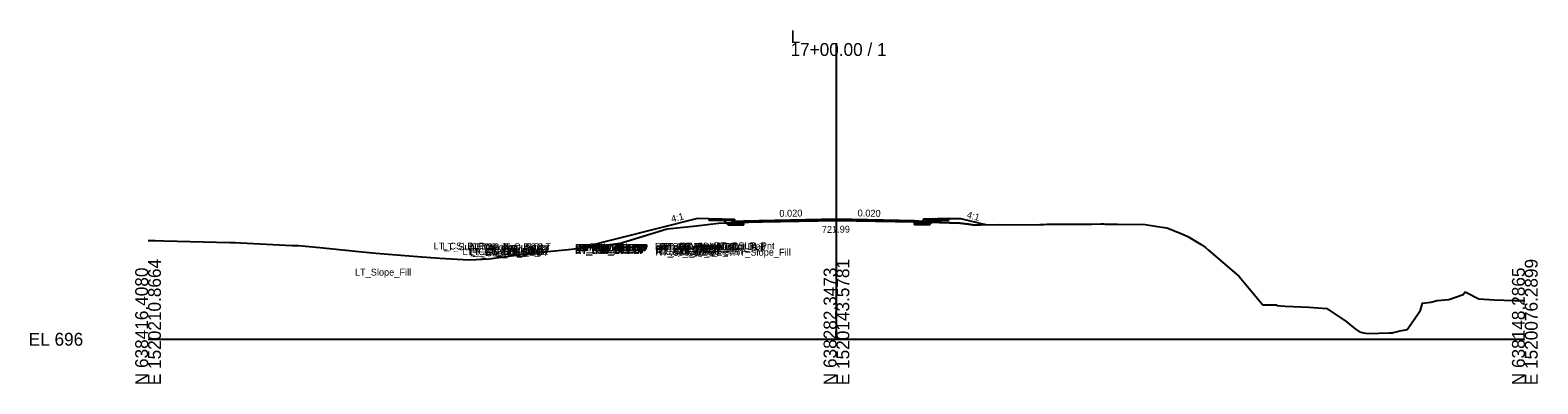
# Model space of a CAD drawing. Extents: x -26 to 3903, y -10 to 9531.
# Drawn here: x -25.7 to 302.8, y 6990.3 to 7067.3 of the extents above; entities that cross this region are included whole.
import ezdxf

# ---------------------------------------------------------------- set-up
doc = ezdxf.new("R2010")
doc.units = 0
for name, color, linetype in [('Default', 7, 'Continuous'), ('Exist Cross Section Cell', 7, 'Continuous'), ('Exist XS Center Line Elevation Label', 7, 'Continuous'), ('Exist XS Ground Line', 7, 'Continuous'), ('Old_Level_63', 7, 'Continuous'), ('Prop CMT Conc Surface', 7, 'Continuous'), ('Prop CMT Pvmt Course 1', 7, 'Continuous'), ('Prop CMT Pvmt Course 1 CG', 7, 'Continuous'), ('Prop CMT Pvmt Course 2', 7, 'Continuous'), ('Prop CMT Pvmt Course 3', 7, 'Continuous'), ('Prop CMT Pvmt Surface', 7, 'Continuous'), ('Prop CMT Slope Grass', 7, 'Continuous'), ('Prop CMT Subgrade Earthwork', 7, 'Continuous'), ('Prop XS Earthwork Shape', 7, 'Continuous'), ('Prop XS SE Text', 7, 'Continuous'), ('Prop XS Side Slope Text', 7, 'Continuous')]:
    doc.layers.add(name, color=color, linetype=linetype)

msp = doc.modelspace()

# ---------------------------------------------------------------- linework, layer by layer
at = {"layer": 'Exist Cross Section Cell'}
for p, q in [((150, 7000), (150, 7064.46)), ((0, 7000), (150, 7000)), ((150, 7000), (300, 7000))]:
    msp.add_line(p, q, dxfattribs=at)
at = {"layer": 'Exist XS Ground Line'}
msp.add_lwpolyline([(0, 7021.49), (0.53, 7021.47), (1.54, 7021.46), (3.41, 7021.42), (17.81, 7021.07), (19, 7021.04), (20.21, 7020.98), (31.36, 7020.42), (32.8, 7020.38), (37.45, 7019.95), (45.2, 7019.18), (49.64, 7018.74), (58.71, 7018), (63.57, 7017.65), (69.89, 7017.26), (71.49, 7017.33), (74.23, 7017.5), (79.68, 7018.24), (80.22, 7018.31), (81.9, 7018.53), (87.14, 7019.09), (91.58, 7019.5), (99.01, 7020.37), (102.77, 7020.89), (102.96, 7020.94), (103.36, 7021.05), (109.58, 7022.93), (113.13, 7024), (119.5, 7024.71), (124.3, 7025.28), (126.6, 7025.35), (127.36, 7025.34), (127.8, 7025.36), (128.35, 7025.38), (129.98, 7025.43), (130.41, 7025.46), (130.82, 7025.46), (131.65, 7025.52), (132.19, 7025.55), (132.5, 7025.55), (133.53, 7025.57), (135.48, 7025.63), (136.32, 7025.65), (137.15, 7025.68), (138.47, 7025.72), (139.13, 7025.74), (140.33, 7025.77), (141.92, 7025.82), (142.73, 7025.84), (144.7, 7025.9), (146.68, 7025.94), (147.49, 7025.96), (148.47, 7025.97), (149.75, 7026), (150.09, 7026), (150.3, 7025.98), (151.52, 7025.97), (153.1, 7025.95), (153.88, 7025.93), (155.89, 7025.89), (157.92, 7025.83), (158.68, 7025.81), (159.84, 7025.79), (160.77, 7025.78), (161, 7025.77), (161.47, 7025.74), (162.66, 7025.7), (164.28, 7025.65), (164.52, 7025.64), (165.01, 7025.62), (167.05, 7025.55), (168.14, 7025.52), (168.57, 7025.51), (168.77, 7025.5), (170.17, 7025.48), (176.87, 7025.25), (178.76, 7025.03), (180.07, 7024.82), (181.45, 7024.92), (185.5, 7025), (191.28, 7024.91), (194.32, 7024.94), (194.58, 7024.97), (195.23, 7024.99), (195.84, 7025.04), (197.24, 7025.06), (198.62, 7025.07), (199.55, 7025.08), (200.01, 7025.08), (201.42, 7025.08), (202.79, 7025.08), (204.14, 7025.08), (205.1, 7025.08), (205.59, 7025.08), (207.61, 7025.09), (208.13, 7025.09), (208.24, 7025.09), (208.55, 7025.08), (209.42, 7025.07), (210.04, 7025.06), (210.82, 7025.06), (210.91, 7025.05), (211.26, 7025.05), (217.28, 7024.98), (219.99, 7024.55), (221.98, 7024.26), (225.13, 7023.03), (226.56, 7022.4), (229.47, 7020.59), (230.45, 7020), (231.05, 7019.36), (237.73, 7013.65), (242.83, 7007.59), (242.9, 7007.5), (242.94, 7007.5), (245.5, 7007.48), (245.9, 7007.47), (246, 7007.33), (247.79, 7007.22), (252.97, 7006.96), (256.88, 7006.73), (261.06, 7003.86), (262.69, 7002.54), (263.05, 7002.29), (264.01, 7001.63), (264.53, 7001.47), (264.83, 7001.41), (265.85, 7001.29), (270.55, 7001.38), (271.2, 7001.43), (271.31, 7001.49), (272.26, 7001.69), (272.45, 7001.77), (274.39, 7002.1), (275.73, 7004.05), (277.25, 7006.36), (277.72, 7007.83), (279.55, 7008.04), (280.89, 7008.43), (283.43, 7008.65), (286.54, 7009.75), (286.91, 7010.24), (287.13, 7010.24), (289.99, 7008.78), (293.3, 7008.59), (297.77, 7008.41), (298.29, 7008.42), (298.33, 7008.42), (300, 7008.42)], dxfattribs=at)
at = {"layer": 'Old_Level_63'}
for p, q in [((127.76, 7026.1), (127.76, 7025.6)), ((127.76, 7025.6), (129.76, 7025.72)), ((167, 7025.78), (169, 7025.66)), ((169, 7025.66), (169, 7026.16)), ((169, 7026.16), (169.5, 7026.16))]:
    msp.add_line(p, q, dxfattribs=at)
for points in [[(122.26, 7025.86), (122.26, 7026.2)], [(127.26, 7025.76), (122.26, 7025.86)], [(127.26, 7026.1), (127.26, 7025.08), (129.76, 7025.13)], [(129.76, 7025.13), (129.76, 7025.72)], [(169.5, 7026.16), (169.5, 7025.15), (167, 7025.2)], [(167, 7025.2), (167, 7025.78)], [(169.5, 7026.16), (169.5, 7025.84)], [(169.5, 7025.84), (174.5, 7025.94)], [(174.5, 7025.94), (174.5, 7026.26)]]:
    msp.add_lwpolyline(points, dxfattribs=at)
at = {"layer": 'Prop CMT Conc Surface'}
for points in [[(127.76, 7025.6), (127.76, 7026.1), (127.26, 7026.1)], [(129.76, 7025.72), (127.76, 7025.6)], [(167, 7025.78), (169, 7025.66)], [(169, 7025.66), (169, 7026.16), (169.5, 7026.16)], [(169.5, 7026.17), (174.5, 7026.27)], [(77.76, 7019.6), (77.76, 7020.1), (77.26, 7020.1)], [(79.76, 7019.72), (77.76, 7019.6)], [(117, 7019.78), (119, 7019.66)], [(119, 7019.66), (119, 7020.16), (119.5, 7020.16)], [(119.5, 7020.17), (124.5, 7020.27)]]:
    msp.add_lwpolyline(points, dxfattribs=at)
at = {"layer": 'Prop CMT Pvmt Course 1'}
for points in [[(150, 7026.12), (129.76, 7025.72)], [(129.76, 7025.47), (150, 7025.87)], [(129.76, 7025.72), (129.76, 7025.47)], [(150, 7025.87), (150, 7026.12)], [(150, 7026.12), (167, 7025.78)], [(150, 7025.87), (150, 7026.12)], [(167, 7025.53), (150, 7025.87)], [(167, 7025.78), (167, 7025.53)]]:
    msp.add_lwpolyline(points, dxfattribs=at)
msp.add_lwpolyline([(150, 7025.87), (150, 7025.99), (150, 7025.99), (150, 7025.87)], close=True, dxfattribs=at)
msp.add_lwpolyline([(150, 7025.87), (150, 7025.99), (150, 7025.99), (150, 7025.87)], close=True, dxfattribs=at)
at = {"layer": 'Prop CMT Pvmt Course 1 CG'}
for points in [[(129.76, 7025.13), (126.76, 7025.07), (126.51, 7024.82)], [(126.51, 7024.82), (129.76, 7024.88)], [(129.76, 7024.88), (129.76, 7025.13)], [(167, 7025.2), (170, 7025.14), (170.26, 7024.88)], [(167, 7024.95), (167, 7025.2)], [(170.26, 7024.88), (167, 7024.95)]]:
    msp.add_lwpolyline(points, dxfattribs=at)
at = {"layer": 'Prop CMT Pvmt Course 2'}
for points in [[(150, 7025.87), (129.76, 7025.47)], [(129.76, 7025.47), (129.76, 7025.13)], [(150, 7025.54), (150, 7025.87)], [(150, 7025.54), (150, 7025.87)], [(150, 7025.87), (167, 7025.53)], [(167, 7025.53), (167, 7025.2)]]:
    msp.add_lwpolyline(points, dxfattribs=at)
at = {"layer": 'Prop CMT Pvmt Course 3'}
for points in [[(129.76, 7025.13), (129.76, 7024.88)], [(150, 7025.29), (150, 7025.54)], [(150, 7025.29), (150, 7025.54)], [(167, 7025.2), (167, 7024.95)]]:
    msp.add_lwpolyline(points, dxfattribs=at)
at = {"layer": 'Prop CMT Pvmt Surface'}
for p, q in [((129.76, 7025.72), (150, 7026.12)), ((150, 7026.12), (167, 7025.78))]:
    msp.add_line(p, q, dxfattribs=at)
for points in [[(150, 7026.12), (129.76, 7025.72)], [(150, 7026.12), (167, 7025.78)]]:
    msp.add_lwpolyline(points, dxfattribs=at)
at = {"layer": 'Prop CMT Slope Grass'}
for p, q in [((119.76, 7026.25), (93.81, 7019.76)), ((177, 7026.31), (182.48, 7024.94))]:
    msp.add_line(p, q, dxfattribs=at)
for points in [[(122.26, 7026.2), (119.76, 7026.25)], [(122.26, 7026.2), (127.26, 7026.1)], [(129.76, 7025.72), (127.76, 7025.6), (127.76, 7026.1), (127.26, 7026.1)], [(167, 7025.78), (169, 7025.66), (169, 7026.16), (169.5, 7026.16)], [(174.5, 7026.26), (169.5, 7026.16)], [(174.5, 7026.26), (177, 7026.31)]]:
    msp.add_lwpolyline(points, dxfattribs=at)
at = {"layer": 'Prop CMT Subgrade Earthwork'}
for points in [[(129.76, 7024.88), (126.51, 7024.82), (125.19, 7026.14)], [(129.76, 7025.47), (129.76, 7024.88)], [(167, 7024.95), (170.26, 7024.88), (171.57, 7026.2)], [(167, 7025.53), (167, 7024.95)]]:
    msp.add_lwpolyline(points, dxfattribs=at)
at = {"layer": 'Prop XS Earthwork Shape'}
for points in [[(119.76, 7026.25), (93.81, 7019.76), (99.01, 7020.37), (102.77, 7020.89), (102.96, 7020.94), (103.36, 7021.05), (109.58, 7022.93), (113.13, 7024), (119.5, 7024.71), (124.3, 7025.28), (125.99, 7025.33), (125.19, 7026.14), (122.26, 7026.2)], [(119.76, 7026.25), (93.81, 7019.76), (99.01, 7020.37), (102.77, 7020.89), (102.96, 7020.94), (103.36, 7021.05), (109.58, 7022.93), (113.13, 7024), (119.5, 7024.71), (124.3, 7025.28), (125.99, 7025.33), (125.19, 7026.14), (122.26, 7026.2)], [(93.81, 7019.76), (99.01, 7020.37), (102.77, 7020.89), (102.96, 7020.94), (103.36, 7021.05), (109.58, 7022.93), (113.13, 7024), (119.5, 7024.71), (124.3, 7025.28), (125.99, 7025.33), (125.19, 7026.14), (122.26, 7026.2), (119.76, 7026.25)], [(160.77, 7025.78), (161, 7025.77), (161.47, 7025.74), (162.66, 7025.7), (164.28, 7025.65), (164.52, 7025.64), (165.01, 7025.62), (167, 7025.53), (168.14, 7025.52), (168.57, 7025.51), (168.77, 7025.5), (170.17, 7025.48), (170.83, 7025.46), (171.58, 7026.21), (169.5, 7026.16), (169, 7026.16), (169, 7025.66), (167, 7025.78), (150, 7026.12), (129.76, 7025.72), (127.76, 7025.6), (127.76, 7026.1), (127.26, 7026.1), (125.19, 7026.14), (125.99, 7025.33), (126.6, 7025.35), (127.36, 7025.34), (127.8, 7025.36), (128.35, 7025.38), (129.76, 7025.43), (129.98, 7025.43), (130.41, 7025.46), (130.82, 7025.46), (131.65, 7025.52), (132.19, 7025.55), (132.5, 7025.55), (133.53, 7025.57), (135.48, 7025.63), (136.32, 7025.65), (137.15, 7025.68), (138.47, 7025.72), (139.13, 7025.74), (140.33, 7025.77), (141.92, 7025.82), (142.73, 7025.84), (144.7, 7025.9), (146.68, 7025.94), (147.49, 7025.96), (148.47, 7025.97), (149.75, 7026), (150.09, 7026), (150.3, 7025.98), (151.52, 7025.97), (153.1, 7025.95), (153.88, 7025.93), (155.89, 7025.89), (157.92, 7025.83), (158.68, 7025.81), (159.84, 7025.79)], [(146.68, 7025.94), (147.49, 7025.96), (148.47, 7025.97), (149.75, 7026), (150.09, 7026), (150.3, 7025.98), (151.52, 7025.97), (153.1, 7025.95), (153.88, 7025.93), (155.89, 7025.89), (157.92, 7025.83), (158.68, 7025.81), (159.84, 7025.79), (160.77, 7025.78), (161, 7025.77), (161.47, 7025.74), (162.66, 7025.7), (164.28, 7025.65), (164.52, 7025.64), (165.01, 7025.62), (167, 7025.53), (168.14, 7025.52), (168.57, 7025.51), (168.77, 7025.5), (170.17, 7025.48), (170.83, 7025.46), (171.58, 7026.21), (169.5, 7026.16), (169, 7026.16), (169, 7025.66), (167, 7025.78), (150, 7026.12), (129.76, 7025.72), (127.76, 7025.6), (127.76, 7026.1), (127.26, 7026.1), (125.19, 7026.14), (125.99, 7025.33), (126.6, 7025.35), (127.36, 7025.34), (127.8, 7025.36), (128.35, 7025.38), (129.76, 7025.43), (129.98, 7025.43), (130.41, 7025.46), (130.82, 7025.46), (131.65, 7025.52), (132.19, 7025.55), (132.5, 7025.55), (133.53, 7025.57), (135.48, 7025.63), (136.32, 7025.65), (137.15, 7025.68), (138.47, 7025.72), (139.13, 7025.74), (140.33, 7025.77), (141.92, 7025.82), (142.73, 7025.84), (144.7, 7025.9)], [(160.77, 7025.78), (161, 7025.77), (161.47, 7025.74), (162.66, 7025.7), (164.28, 7025.65), (164.52, 7025.64), (165.01, 7025.62), (167, 7025.53), (168.14, 7025.52), (168.57, 7025.51), (168.77, 7025.5), (170.17, 7025.48), (170.83, 7025.46), (171.58, 7026.21), (169.5, 7026.16), (169, 7026.16), (169, 7025.66), (167, 7025.78), (150, 7026.12), (129.76, 7025.72), (127.76, 7025.6), (127.76, 7026.1), (127.26, 7026.1), (125.19, 7026.14), (125.99, 7025.33), (126.6, 7025.35), (127.36, 7025.34), (127.8, 7025.36), (128.35, 7025.38), (129.76, 7025.43), (129.98, 7025.43), (130.41, 7025.46), (130.82, 7025.46), (131.65, 7025.52), (132.19, 7025.55), (132.5, 7025.55), (133.53, 7025.57), (135.48, 7025.63), (136.32, 7025.65), (137.15, 7025.68), (138.47, 7025.72), (139.13, 7025.74), (140.33, 7025.77), (141.92, 7025.82), (142.73, 7025.84), (144.7, 7025.9), (146.68, 7025.94), (147.49, 7025.96), (148.47, 7025.97), (149.75, 7026), (150.09, 7026), (150.3, 7025.98), (151.52, 7025.97), (153.1, 7025.95), (153.88, 7025.93), (155.89, 7025.89), (157.92, 7025.83), (158.68, 7025.81), (159.84, 7025.79)], [(128.35, 7025.38), (129.76, 7025.43), (129.76, 7024.88), (126.51, 7024.82), (125.99, 7025.33), (126.6, 7025.35), (127.36, 7025.34), (127.8, 7025.36)], [(129.76, 7024.88), (126.51, 7024.82), (125.99, 7025.33), (126.6, 7025.35), (127.36, 7025.34), (127.8, 7025.36), (128.35, 7025.38), (129.76, 7025.43)], [(129.76, 7024.88), (126.51, 7024.82), (125.99, 7025.33), (126.6, 7025.35), (127.36, 7025.34), (127.8, 7025.36), (128.35, 7025.38), (129.76, 7025.43)], [(170.17, 7025.48), (170.83, 7025.46), (170.26, 7024.88), (167, 7024.95), (167, 7025.53), (168.14, 7025.52), (168.57, 7025.51), (168.77, 7025.5)], [(167, 7024.95), (170.26, 7024.88), (170.83, 7025.46), (170.17, 7025.48), (168.77, 7025.5), (168.57, 7025.51), (168.14, 7025.52), (167, 7025.53)], [(167, 7024.95), (170.26, 7024.88), (170.83, 7025.46), (170.17, 7025.48), (168.77, 7025.5), (168.57, 7025.51), (168.14, 7025.52), (167, 7025.53)], [(171.58, 7026.21), (174.5, 7026.27), (177, 7026.31), (182.48, 7024.94), (181.45, 7024.92), (180.07, 7024.82), (178.76, 7025.03), (176.87, 7025.25), (170.83, 7025.46)], [(177, 7026.31), (182.48, 7024.94), (181.45, 7024.92), (180.07, 7024.82), (178.76, 7025.03), (176.87, 7025.25), (170.83, 7025.46), (171.58, 7026.21), (174.5, 7026.27)], [(174.5, 7026.27), (177, 7026.31), (182.48, 7024.94), (181.45, 7024.92), (180.07, 7024.82), (178.76, 7025.03), (176.87, 7025.25), (170.83, 7025.46), (171.58, 7026.21)]]:
    msp.add_lwpolyline(points, close=True, dxfattribs=at)

# ---------------------------------------------------------------- texts
at = {"layer": 'Default'}
msp.add_text('-', height=0.0001, dxfattribs=at).set_placement((0, 7000))
at = {"layer": 'Exist Cross Section Cell'}
for s, p in [('L', (140, 7064.46)), ('17+00.00 / 1', (140, 7061.66)), ('EL 696', (-26, 6998.6))]:
    msp.add_text(s, height=2.8, dxfattribs=at).set_placement(p)
for s, p in [('N 638416.4080', (0, 6990)), ('E 1520210.8664', (2.8, 6990)), ('N 638282.3473', (150, 6990)), ('E 1520143.5781', (152.8, 6990)), ('N 638148.2865', (300, 6990)), ('E 1520076.2899', (302.8, 6990))]:
    msp.add_text(s, height=2.8, rotation=90, dxfattribs=at).set_placement(p)
at = {"layer": 'Exist XS Center Line Elevation Label'}
msp.add_text('721.99', height=1.5, rotation=0.8401, dxfattribs=at).set_placement((146.82, 7023.13))
at = {"layer": 'Prop CMT Conc Surface'}
for s, p in [('LT_CSLP_Pnt', (62.21, 7019.54)), ('LT_Sub_Trench_Out_DLT', (64.16, 7019.39)), ('LT_CG_Top_BOC', (69.62, 7019.35)), ('LT_CG_Top_Face', (70.14, 7019.35)), ('RT_PV1_OEEOP', (93.18, 7019.24)), ('LT_PV1_OEEOP', (93.27, 7019.24)), ('RT_PV1_IEEOP', (93.75, 7019.24)), ('LT_PV1_IEEOP', (93.84, 7019.24)), ('PV1_PGL', (96.2, 7019.37)), ('RT_Sub_Trench_Out_DLT', (110.46, 7019.45)), ('RT_CG_Top_Face', (111.29, 7019.41)), ('RT_SDWK_In_Top', (111.71, 7019.42)), ('RT_CG_Top_BOC', (111.77, 7019.41)), ('RT_SDWK_Out_Top', (115.85, 7019.52)), ('RT_CSLP_Pnt', (123.36, 7019.6)), ('LT_CG1_Shelf_Out', (68.5, 7018.32)), ('LT_CG_Bot_BOC', (69.83, 7018.33)), ('LT_Sub_OEOP', (70.16, 7018.07)), ('LT_CG_Top_Gut', (70.54, 7018.85)), ('LT_PV2_OEOT', (73.38, 7018.72)), ('LT_PV3_OEOT', (73.38, 7018.38)), ('LT_Sub_OEOT', (73.42, 7018.13)), ('LT_PV1_OEOT', (73.56, 7018.97)), ('LT_CG_Bot_IE', (73.64, 7018.38)), ('RT_PV2_OEEOP', (93, 7019.12)), ('RT_PV3_OEEOP', (93, 7018.79)), ('RT_Sub_OEEOP', (93.04, 7018.54)), ('LT_PV2_OEEOP', (93.09, 7019.12)), ('LT_PV3_OEEOP', (93.09, 7018.79)), ('LT_Sub_OEEOP', (93.12, 7018.54)), ('RT_PV2_IEEOP', (93.57, 7019.12)), ('LT_PV2_IEEOP', (93.66, 7019.12)), ('PV2_PGL', (96.03, 7019.12)), ('RT_PV2_OEOT', (110.53, 7018.78)), ('RT_PV3_OEOT', (110.53, 7018.45)), ('RT_Sub_OEOT', (110.56, 7018.2)), ('RT_PV1_OEOT', (110.71, 7019.03)), ('RT_CG_Bot_IE', (110.79, 7018.45)), ('RT_CG1_Shelf_Out', (111.64, 7018.39)), ('RT_CG_Top_Gut', (111.69, 7018.91)), ('RT_SDWK_In_Bot', (111.9, 7019.09)), ('RT_CG_Bot_BOC', (111.98, 7018.4)), ('RT_Sub_OEOP', (113.81, 7018.13)), ('RT_SDWK_Out_Bot', (116.03, 7019.19)), ('RT_Slope_Fill', (127.46, 7018.2)), ('LT_Slope_Fill', (45.07, 7013.85))]:
    msp.add_text(s, height=1.5, dxfattribs=at).set_placement(p)
at = {"layer": 'Prop XS SE Text'}
for rotation, p in [(1.1458, (137.57, 7026.63)), (358.8542, (154.6, 7026.74))]:
    msp.add_text('0.020', height=1.5, rotation=rotation, dxfattribs=at).set_placement(p)
at = {"layer": 'Prop XS Side Slope Text'}
for rotation, p in [(14.0362, (114.17, 7025.43)), (344.7445, (178.3, 7026.46))]:
    msp.add_text('4:1', height=1.5, rotation=rotation, dxfattribs=at).set_placement(p)

doc.saveas('drawing.dxf')
